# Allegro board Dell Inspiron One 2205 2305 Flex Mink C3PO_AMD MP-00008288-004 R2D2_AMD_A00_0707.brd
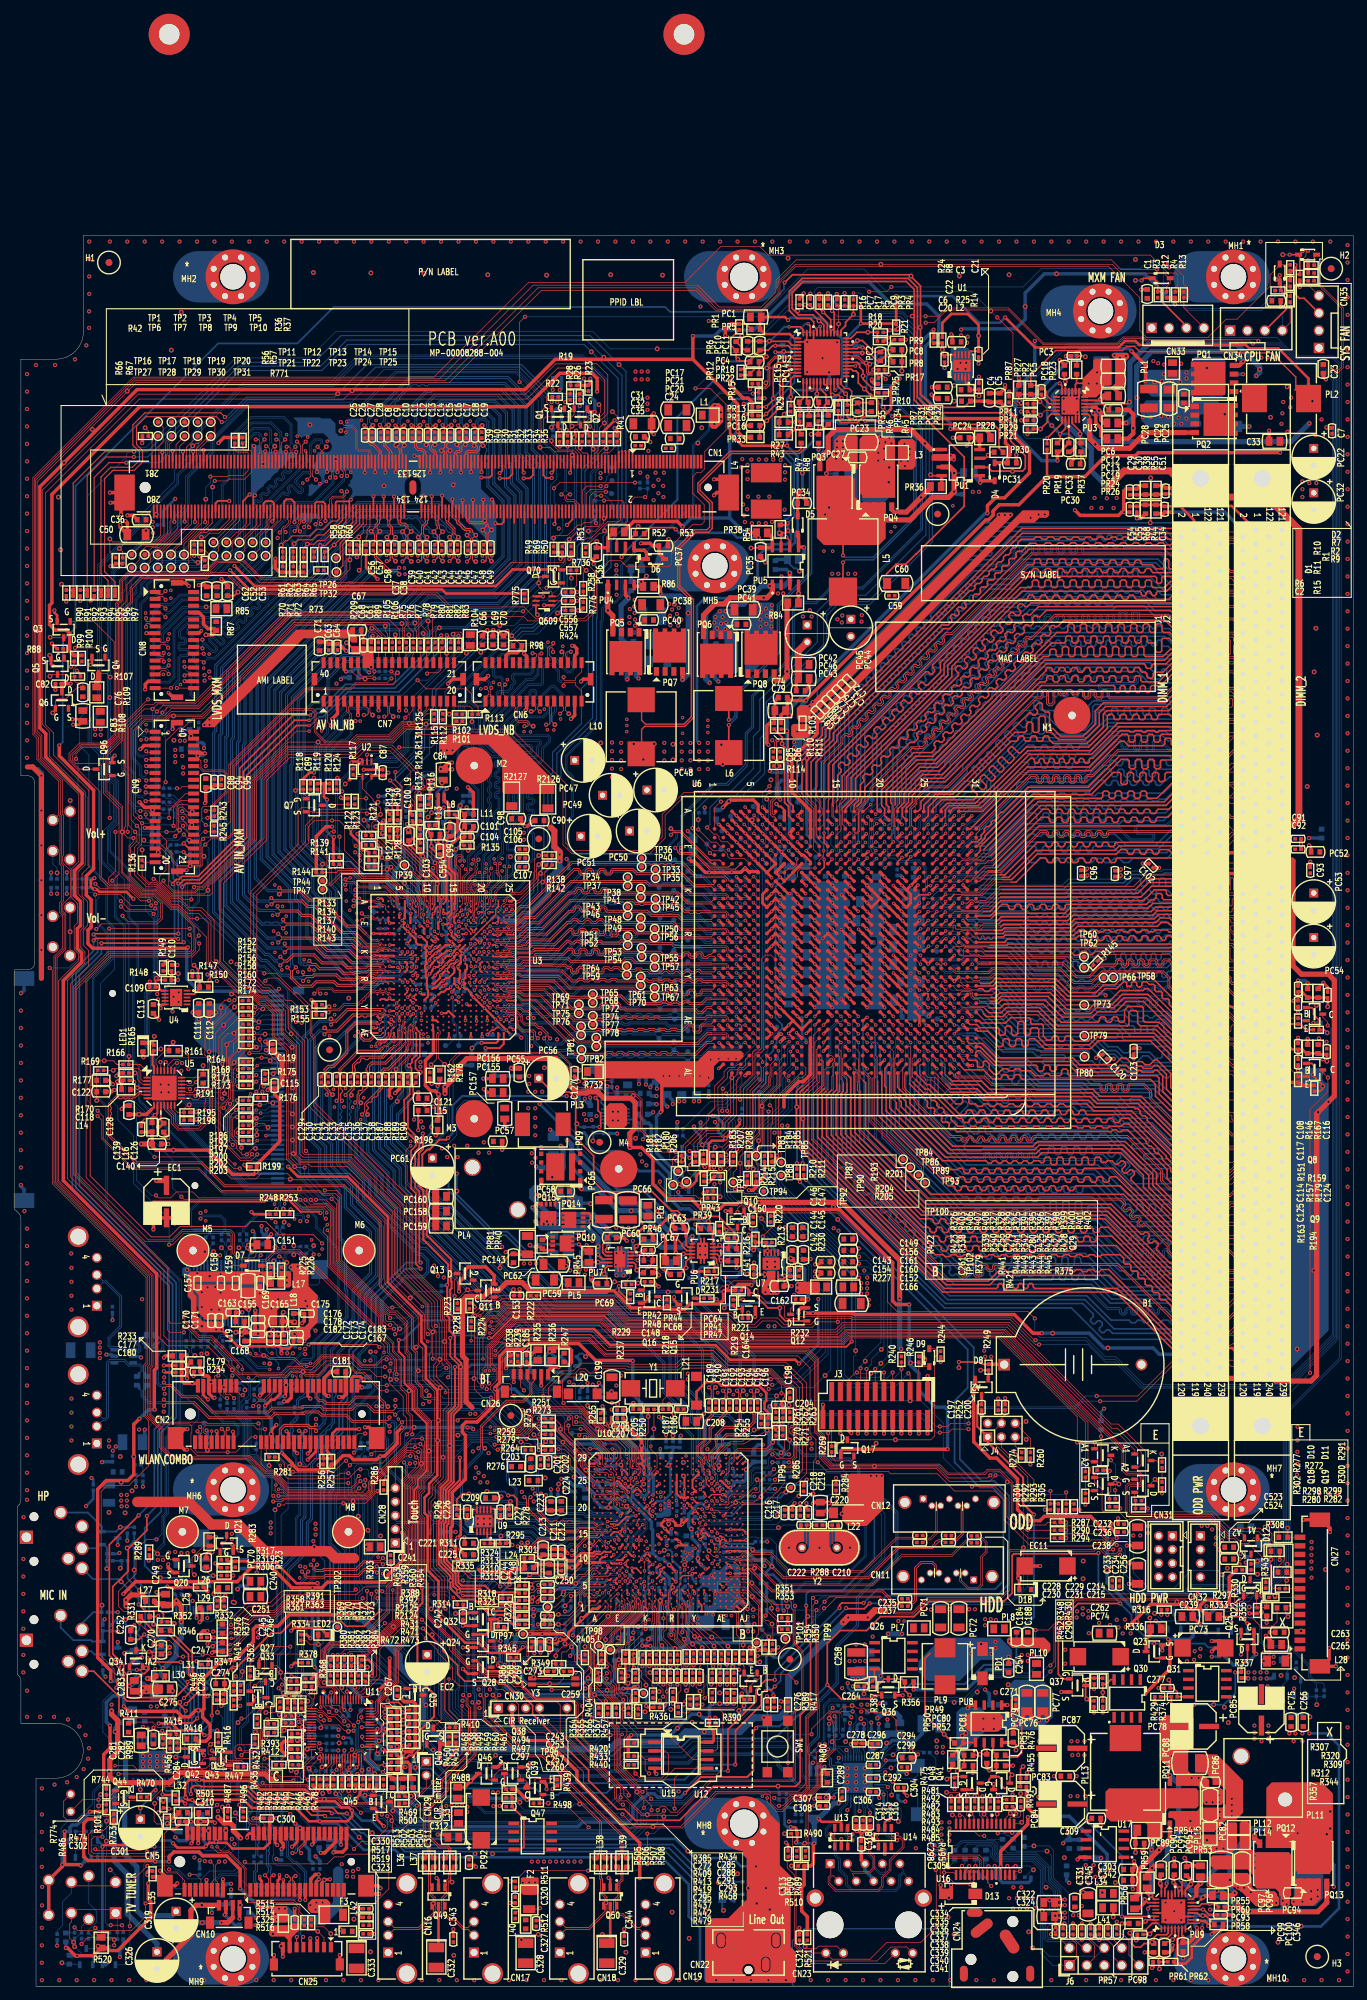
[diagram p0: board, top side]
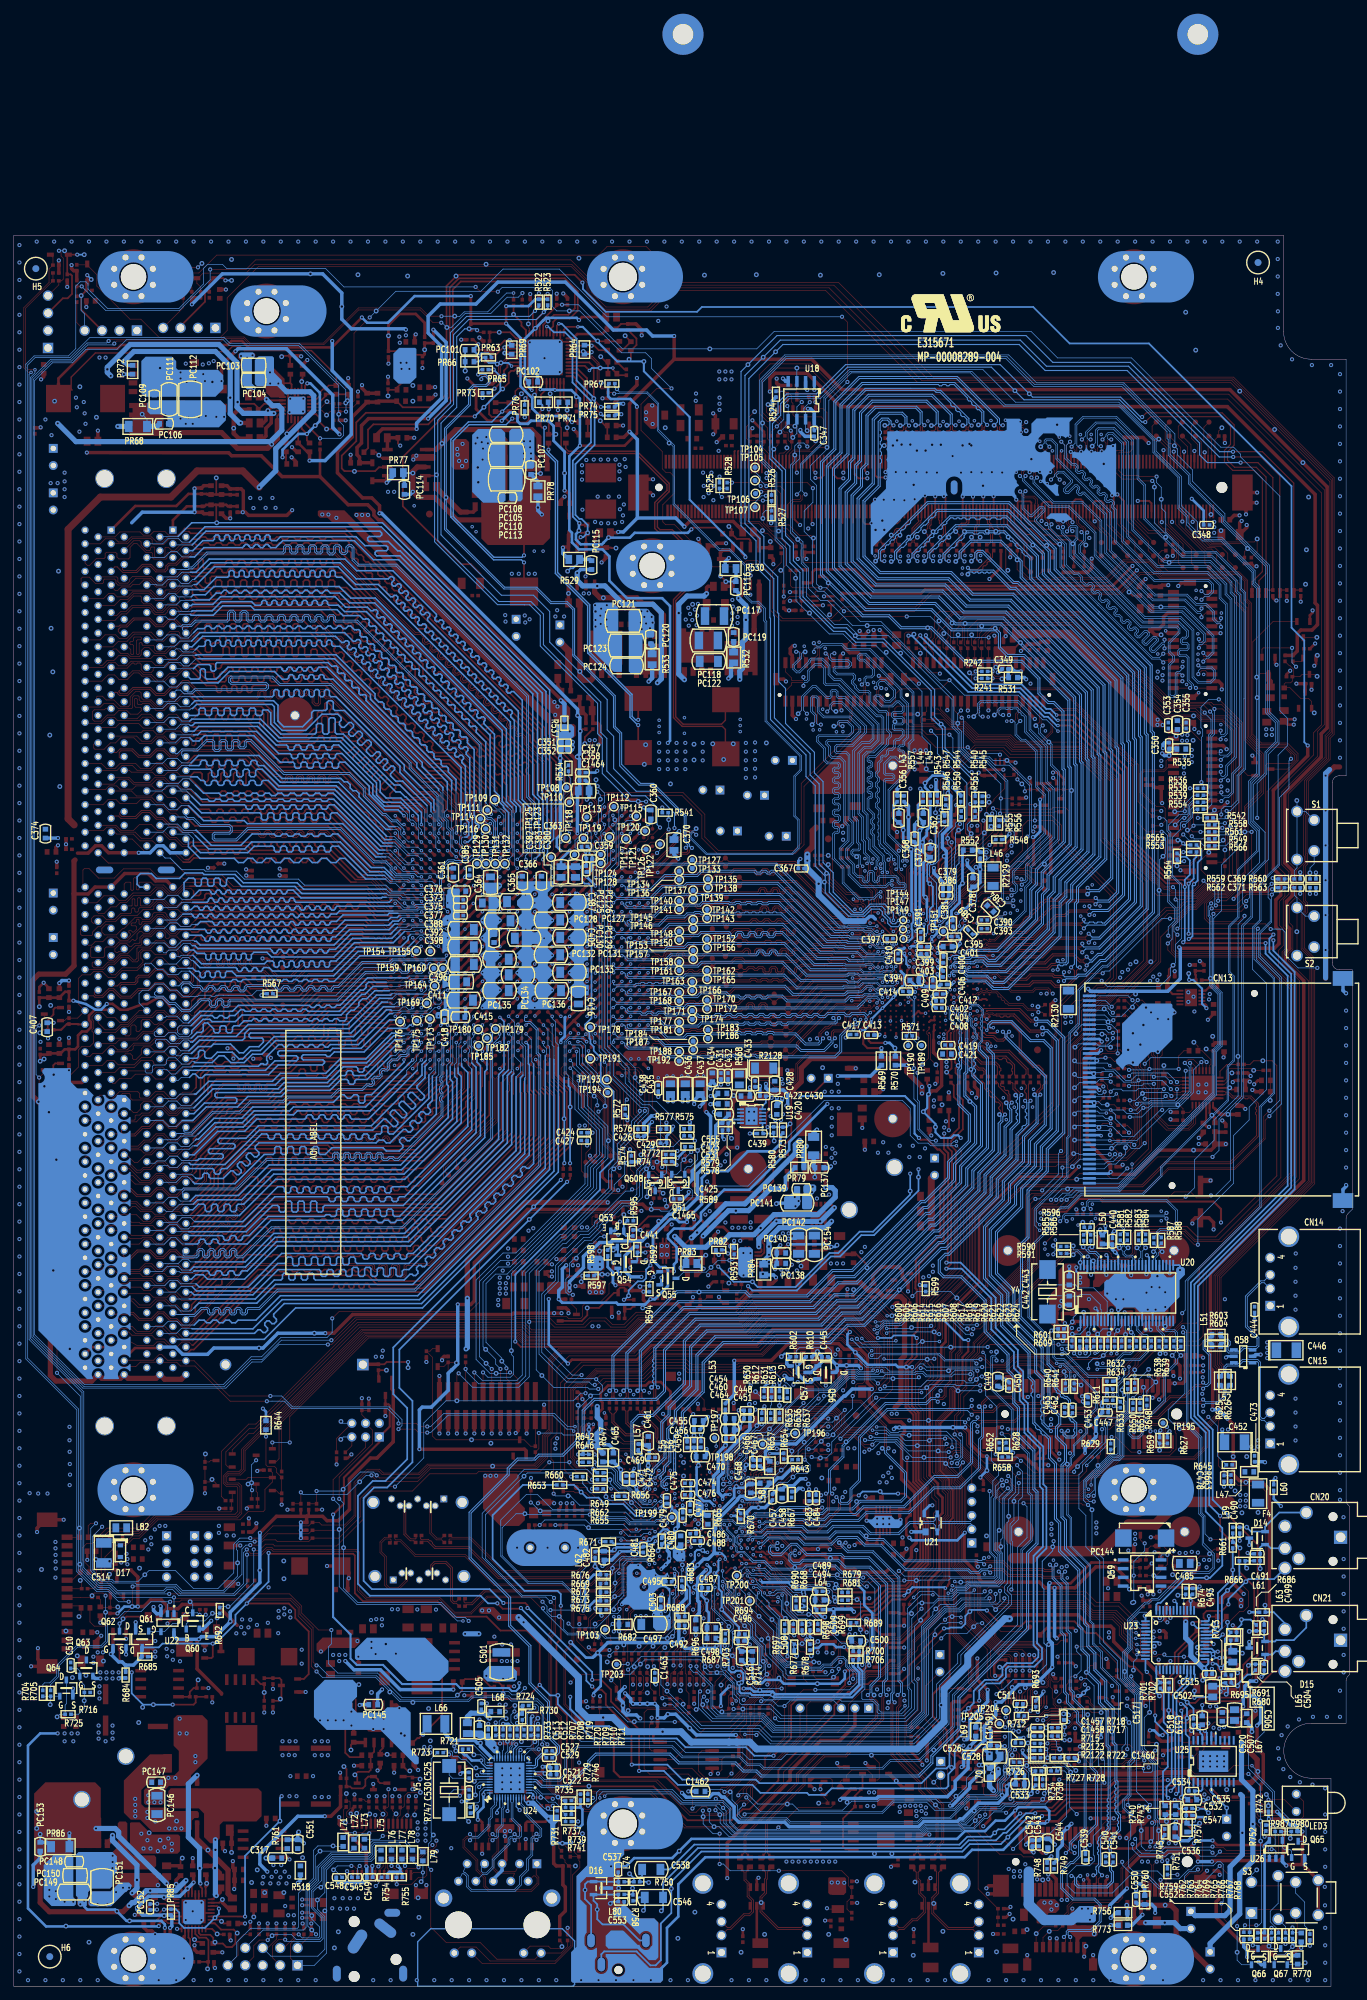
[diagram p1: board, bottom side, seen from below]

Outline 195 x 255 mm; copper layers: TOP, GND1, INT1, VCC, GND2, BOTTOM. Coordinates in mm from the lower left corner of the outline.
Outline path: 0,148.07 0,113.17 0.61,112.56 arc(0.82,112.24) 0.9,111.86 0.9,70.81 arc(0.82,70.43) 0.61,70.11 0.4,69.9 0.4,45.4 0.61,45.19 arc(0.82,44.87) 0.9,44.49 0.9,38.31 6,38.31 arc(10,34.31) 6,30.31 3.1,30.31 3.1,0 195,0 195,255 10,255 10,241 arc(8.83,238.17) 6,237 0.9,237 0.9,176.32 1.9,176.32 arc(2.61,176.03) 2.9,175.32 2.9,149.07 arc(2.61,148.36) 1.9,148.07 0,148.07

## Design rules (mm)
net group AMP_SVRR: nets AMP_SVRR N214468883
net group AU6433_RST_N: nets AU6433_RST_N N182697602
net group BLK_EN: nets BLK_EN N214902576
net group BLK_PWM: nets BLK_PWM N214902487
net group BT_DISABLE: nets BT_DISABLE BT_DISABLE_R
net group BT_DISABLE_N: nets BT_DISABLE_N N212412188
net group BT_LED: nets BT_LED N201793917
net group CARDREADER-MISC_12/12/12/A: nets SDCLK/XDALE/MSBS SDWP/XDCLE/MSCLK
net group CIR_BLTX_TIP_DRIVE: nets CIR_BLTX_TIP_DRIVE N195279140
net group COM1_C1N: nets COM1_C1N COM1_C1P
net group COM1_C2N: nets COM1_C2N COM1_C2P
net group COM1_RI_N: nets COM1_RI_N N216543933
net group CPU_FAN_PWM: nets CPU_FAN_PWM N201366217
net group CPU_PWRGD: nets N192993994 SYS_PWROK
net group CPU_TEST29_H_FBCLKOUT_H: nets CPU_TEST29_H_FBCLKOUT_H CPU_TEST29_L_FBCLKOUT_L
net group CTSA: nets CTSA CTSA_L
net group DCDA: nets DCDA DCDA_L
net group DDR3_P1V5_CS: nets DDR3_P1V5_CS DDR3_P1V5_FILT
net group DDSPC_HPD: nets DDSPC_HPD MXM_DDSPC_HPD
net group DSRA: nets DSRA DSRA_L
net group DTRA: nets DTRA DTRA_L
net group EAPD_MUTE_CTRL: nets EAPD_MUTE_CTRL N222289486
net group EEDO_LED3: nets EEDO_LED3 EEDO_LED3_R
net group EESK_LED1: nets EESK_LED1 EESK_LED1_R
net group FC_CLK_R: nets FC_CLK_R N182610771
net group FC_FBCLKOUT_R: nets FC_FBCLKOUT_R N182623261
net group GPON7: nets GPON7 N182698044
net group HDA_SPKR: nets N215117175 N224524412
net group HT_CTLIN1: nets HT_CTLIN1_N HT_CTLIN1_P
net group HT_CTLOUT1: nets HT_CTLOUT1_N HT_CTLOUT1_P
net group I2C_CLK: nets N184743934 NB_LCD_DDC_CLK
net group I2C_DATA: nets N184744092 NB_LCD_DDC_DATA
net group IHDA-ANALOG: nets JDREF_AUD N207033685
net group IHDA-ANALOG1_10/10/20/A: nets N199565995 N199565999
net group LAN_ACT_LED_N: nets LAN_ACT_LED_N LAN_ACT_LED_R_N
net group LAN_EVDD10: nets LAN_EVDD10 LAN_REGOUT
net group LED_AMBER_EN: nets LED_AMBER_EN N220115319
net group LVDDPWR_R_EN: nets LVDDPWR_R_EN N214797167
net group MIC_CLK: nets MIC_CLK MIC_CLK_R
net group MIC_DAT: nets MIC_DAT MIC_DAT_R
net group MISC-SPIFLASH: nets SPI_CLK SPI_CS_N
net group MXM_BLEN: nets MXM_BLEN N87830784
net group MXM_LVDS_DDC_CLK: nets MXM_LVDS_DDC_CLK N195453329
net group MXM_LVDS_DDC_DATA: nets MXM_LVDS_DDC_DATA N200059938
net group MXM_LVDS_PWM: nets MXM_LVDS_PWM N87830775
net group MXM_LVDSPWR_EN: nets MXM_LVDSPWR_EN N87830786
net group N192922017: nets N192922017 N192922462
net group N192922021: nets N192922021 N192922350
net group N192993947: nets N192993947 N192994078
net group N192994193: nets N192994193 N192994205
net group N192994229: nets N192994229 N192994300
net group N193056479: nets N193056479 N193056523
net group N193057135: nets N193057135 N193057441
net group N193064874: nets N193064874 N193064914
net group N193065496: nets N193065496 N197768843
net group N193065687: nets N193065687 N193065695
net group N193065785: nets N193065785 N193065828
net group N193066341: nets N193066341 N193066412
net group N193082220: nets N193082220 N193082234
net group N204332065: nets N204332065 N204332072
net group N208253507: nets N208253507 N208253520
net group NB_LCD_BKL_EN: nets NB_LCD_BKL_EN NB_LCD_BKL_EN_R
net group NB_LCD_BKL_PWM: nets NB_LCD_BKL_PWM NB_LCD_BKL_PWM_R
net group NB_LCD_PWR_EN: nets NB_LCD_PWR_EN NB_LCD_PWR_EN_R
net group P1V1_PWRGD: nets N204331910 P1V1_PWRGD
net group P1V5_DDR3_PWRGD: nets N205761624 P1V5_DDR3_PWRGD
net group P1V25_PWRGD: nets N192993988 P1V25_PWRGD
net group P2E_SLOT0_PRSNT_1_N: nets P2E_SLOT0_PRSNT_1_N P2E_SLOT0_PRSNT_1_N_R
net group P3V3_BAT: nets P3V3_BAT VBAT
net group P3V3_CARD: nets P3V3_CARD P3V3_CF33
net group P5V_USB5V1: nets USB_OC1 USB_OCP_2_4
net group P5V_USB5V3: nets USB_OC2 USB_OCP_5_9
net group P12V_STBY: nets N193082214 N193082230
net group P19V_CONVERTER: nets N215339663 N218776850
net group P19V_SYS_FILE: nets N193056457 P19V_SYS_FILE
net group PANEL_ID0: nets PANEL_ID0 PANEL_ID0_R
net group PANEL_ID1: nets PANEL_ID1 PANEL_ID1_R
net group PANEL_ID2: nets PANEL_ID2 PANEL_ID2_R
net group PCI_AD29: nets PCI_AD29 SB800_MEMHOT_N
net group PCIE-MISC_W4/A_PH: nets PCIE_CALRN_R PCIE_CALRP_R
net group PSON_N_1V5_CTRL: nets N193066078 PSON_N_1V5_CTRL
net group PSON_N_3V3_CTRL: nets N187384381 PSON_N_3V3_CTRL
net group PSON_N_5V_CTRL: nets N187384477 PSON_N_5V_CTRL
net group PSON_N_12V_CTRL: nets N211486769 PSON_N_12V_CTRL
net group PWRGD_PS: nets N188975577 PWRGD_PS
net group RIA: nets RIA RIA_L
net group RTSA: nets RTSA RTSA_L
net group RXDA: nets RXDA RXDA_L
net group SATA-CAL_W12.6-11/A_PH: nets SATA_CALRN SATA_CALRP
net group SB_PWRGD: nets N194724824 N222245969
net group SB_RTCRST_N: nets SB_RTCRST_N VBAT_IN
net group SD_D0/MMC_D0/MS_D0/XD_D0: nets N182697773 SD_D0/MMC_D0/MS_D0/XD_D0
net group SD_D3/MMC_D3/MS_D3/XD_D3: nets N182697771 SD_D3/MMC_D3/MS_D3/XD_D3
net group SD_D4/MMC_D4/MS_D4/XD_D4: nets N182697757 SD_D4/MMC_D4/MS_D4/XD_D4
net group SD_D5/MMC_D5/MS_D5/XD_D5: nets N182697749 SD_D5/MMC_D5/MS_D5/XD_D5
net group SD_D6/MMC_D6/MS_D6/XD_D6: nets N182697751 SD_D6/MMC_D6/MS_D6/XD_D6
net group SD_D7/MMC_D7/MS_D7/XD_D7: nets N182697755 SD_D7/MMC_D7/MS_D7/XD_D7
net group SDCDN/XDWRN: nets N182697812 SDCDN/XDWRN
net group SDCMD/XDRBN: nets N182697816 SDCMD/XDRBN
net group SIO_CIR_TX: nets N195279187 SIO_CIR_TX
net group SIO_KBCLK: nets N225179540 SIO_KBCLK
net group SIO_KBDATA: nets N225179544 SIO_KBDATA
net group SIO_MSECLK: nets N225179532 SIO_MSECLK
net group SIO_MSEDATA: nets N225179536 SIO_MSEDATA
net group SPDIF-OUT: nets SPDIF-OUT_MXM_R SPDIF-OUT_NB_R
net group SPEK_SUMOUT_L: nets SPEK_SUMOUT_L SUMOUT_L
net group SPI_DATAIN: nets SPI_DATAIN SPI_DI_R
net group SPM_CLKN: nets SPM_CLKN SPM_CLKP
net group SYS_FAN1_PWM: nets N208745698 SYS_FAN1_PWM
net group SYS_FAN_PWM: nets N201366255 SYS_FAN_PWM
net group TOUCH_PANEL_DETECT: nets N198554672 TOUCH_PANEL_DETECT
net group TXDA: nets TXDA TXDA_L
net group USB5V2: nets USB_OC0 USB_OCP_0_6
net group VDD0_NB_ENABLE: nets N192994176 VDD0_NB_ENABLE
net group VDDIO_P3V3_PCIGP: nets VDDIO_P3V3_PCIGP VDDPL_P3V3_SYS
net group VGA-DDC_W6.5/A_PH: nets MXM_VGA_DDC_CLK MXM_VGA_DDC_DATA
net group VRM_PWRGD: nets N194724769 VRM_PWRGD
net group XDWPN: nets N182697814 XDWPN
net group 2668_BK_ENA: nets 2668_BK_ENA 2668_BK_ENA_MXM_R 2668_BK_ENA_NB_R DDR3_P1V5_EN_S3 ENABKL ENABKL_R GPIO208_MXM_R GPIO208_NB_N N174239814 N214468931 N215339673 SLP_S3_N
net group 2668_BK_PWM: nets 2668_BK_PWM 2668_BK_PWM_MXM_R 2668_BK_PWM_NB_R BKL_PWM_R BRIGHT_ADJUST
net group 2668_DETECT_N: nets 2668_DETECT_N 2668_DETECT_N_MXM_R 2668_DETECT_N_NB_R
net group 2668_LVDD_EN: nets 2668_LVDD_EN 2668_LVDD_EN_MXM_R 2668_LVDD_EN_NB_R LVDDPWR_EN
net group AMP_IN_L: nets AMP_IN_L INL INL_MXM_R INL_NB_R
net group AMP_IN_R: nets AMP_IN_R INR_MXM_R INR_NB_R SPEK_SUMOUT_R SUMOUT_R
net group AMP_MODE: nets AMP_MODE N214468911 N214485400
net group AP_VOLUME_DOWN: nets AP_VOLUME_DOWN AP_VOLUME_DOWN_MXM_R AP_VOLUME_DOWN_NB_R
net group AP_VOLUME_UP: nets AP_VOLUME_UP AP_VOLUME_UP_MXM_R AP_VOLUME_UP_NB_R
net group AUDIO_INDICATE: nets AUDIO_INDICATE AUDIO_INDICATE_MXM_R AUDIO_INDICATE_NB_R
net group AUDIO_MUTE: nets AUDIO_MUTE AUDIO_MUTE_MXM_R AUDIO_MUTE_NB_R
net group AV_MODE: nets AV_MODE AV_MODE_MXM_R AV_MODE_NB_R
net group AZ_SDATA_OUT: nets P1V5_TV P1V5_WW SB_AZ_VDDIO SPM_COMPN VDDIO_AZ_S
net group CLK-14_W5.1-4.5/A_PH: nets CLK_REQG_N MXM_CLKREQ_N NB_OSC NB_OSC_R SB_OSC SB_OSC_R
net group CLK-33_W4-3.5/A_PH: nets CLK_PCI_33M_DEBUG CLK_PCI_33M_DEBUG_R CLK_PCI_33M_SIO PCI_CLK0 PCI_CLK1_R PCI_CLK2 PCI_CLK2_R PCI_CLK3 PCI_CLK3_R PCI_CLK4 PCI_CLK4_R
net group CLK-48_W5.1-4.5/A_PH: nets CLK_48M_CARD CLK_48M_SIO CLK_48M_USB N182698057 USB_48M_R
net group CLK-HOST_W5-4D6.2-5.5/A_PH: nets CLK_200M_CPU_DN CLK_200M_CPU_DN_R CLK_200M_CPU_DP CLK_200M_CPU_DP_R CPU_CLKIN_SC_N CPU_CLKIN_SC_P
net group CLK-SRC_W3.9-3.5D6.1-6/A_PH: nets CLK_100M_NBGFX_DN CLK_100M_NBGFX_DP CLK_100M_NBHT_DN CLK_100M_NBHT_DP CLK_100M_PCIE_LAN_DN CLK_100M_PCIE_LAN_DP CLK_100M_PCIE_TUNER_DN CLK_100M_PCIE_TUNER_DP CLK_100M_PCIE_WLAN_DN CLK_100M_PCIE_WLAN_DP GFX_CLK_DN GFX_CLK_DP NBLINK_RCLK_DN NBLINK_RCLK_DP SB_SRC_CLK_DN SB_SRC_CLK_DP
net group CLK-XTAL_W4-3.5/A_PH: nets 32K_X1 32K_X2 CLK_ICH_RTCX1 CLK_ICH_RTCX2 LAN_XTAL1 LAN_XTAL2 SATA_X1 SATA_X2
net group CLK_VDD: nets CLK_VDD PD# REF0/SEL_HTT6
net group CPU_CORE_TYPE: nets N192994066
net group CPU_HTREF1: nets N193064906
net group CPU_THERMDA: nets P3V3_AVCC_SIO REMOTE_P SIO_GND SIO_P5V_SENSE VREF_SIO
net group CPU_THERMTRIP_N: nets CPU_THERMTRIP_N CPU_THERMTRIP_R_N N221267533
net group CPU_VDDA_RUN_OUT: nets N193065820
net group DCIN: nets DCIN N192917727 VIN_19
net group DDR3_P1V5_DH: nets DDR3_P1V5_DH DDR3_P1V5_VBST N193073747 N193074055 N193074069
net group DDR3_P1V5_EN_S5: nets N212418796
net group DDR3A-ADDCMD_W9/B_PH: nets MEM_MA_ADD0 MEM_MA_ADD1 MEM_MA_ADD2 MEM_MA_ADD3 MEM_MA_ADD4 MEM_MA_ADD5 MEM_MA_ADD6 MEM_MA_ADD7 MEM_MA_ADD8 MEM_MA_ADD9 MEM_MA_ADD10 MEM_MA_ADD11 MEM_MA_ADD12 MEM_MA_ADD13 MEM_MA_ADD14 MEM_MA_ADD15 MEM_MA_BANK0 MEM_MA_BANK1 MEM_MA_BANK2 MEM_MA_CAS_N MEM_MA_RAS_N MEM_MA_WE_N
net group DDR3A-CLK_W5.1D5.6/B_PH: nets MEM_MA0_CLK0_N MEM_MA0_CLK0_P MEM_MA0_CLK1_N MEM_MA0_CLK1_P
net group DDR3A-CTRL_W9/B_PH: nets MEM_MA0_CS_L0 MEM_MA0_CS_L1 MEM_MA0_ODT0 MEM_MA0_ODT1 MEM_MA_CKE0 MEM_MA_CKE1
net group DDR3A-DQ_W9/B_PH: nets MEM_MA_CHECK0 MEM_MA_CHECK1 MEM_MA_CHECK2 MEM_MA_CHECK3 MEM_MA_CHECK4 MEM_MA_CHECK5 MEM_MA_CHECK6 MEM_MA_CHECK7 MEM_MA_DATA0 MEM_MA_DATA1 MEM_MA_DATA2 MEM_MA_DATA3 MEM_MA_DATA4 MEM_MA_DATA5 MEM_MA_DATA6 MEM_MA_DATA7 MEM_MA_DATA8 MEM_MA_DATA9 MEM_MA_DATA10 MEM_MA_DATA11 MEM_MA_DATA12 MEM_MA_DATA13 MEM_MA_DATA14 MEM_MA_DATA15 MEM_MA_DATA16 MEM_MA_DATA17 MEM_MA_DATA18 MEM_MA_DATA19 MEM_MA_DATA20 MEM_MA_DATA21 MEM_MA_DATA22 MEM_MA_DATA23 MEM_MA_DATA24 MEM_MA_DATA25 MEM_MA_DATA26 MEM_MA_DATA27 MEM_MA_DATA28 MEM_MA_DATA29 MEM_MA_DATA30 MEM_MA_DATA31 MEM_MA_DATA32 MEM_MA_DATA33 MEM_MA_DATA34 MEM_MA_DATA35 MEM_MA_DATA36 MEM_MA_DATA37 MEM_MA_DATA38 MEM_MA_DATA39 MEM_MA_DATA40 MEM_MA_DATA41 MEM_MA_DATA42 MEM_MA_DATA43 MEM_MA_DATA44 MEM_MA_DATA45 MEM_MA_DATA46 MEM_MA_DATA47 MEM_MA_DATA48 MEM_MA_DATA49 MEM_MA_DATA50 MEM_MA_DATA51 MEM_MA_DATA52 MEM_MA_DATA53 MEM_MA_DATA54 MEM_MA_DATA55 MEM_MA_DATA56 MEM_MA_DATA57 MEM_MA_DATA58 MEM_MA_DATA59 MEM_MA_DATA60 MEM_MA_DATA61 MEM_MA_DATA62 MEM_MA_DATA63 MEM_MA_DM0 MEM_MA_DM1 MEM_MA_DM2 MEM_MA_DM3 MEM_MA_DM4 MEM_MA_DM5 MEM_MA_DM6 MEM_MA_DM7 MEM_MA_DM8
net group DDR3A-DQS_W5.1D5.6/B_PH: nets MEM_MA_DQS0_N MEM_MA_DQS0_P MEM_MA_DQS1_N MEM_MA_DQS1_P MEM_MA_DQS2_N MEM_MA_DQS2_P MEM_MA_DQS3_N MEM_MA_DQS3_P MEM_MA_DQS4_N MEM_MA_DQS4_P MEM_MA_DQS5_N MEM_MA_DQS5_P MEM_MA_DQS6_N MEM_MA_DQS6_P MEM_MA_DQS7_N MEM_MA_DQS7_P MEM_MA_DQS8_N MEM_MA_DQS8_P
net group DDR3B-ADDCMD_W9/T_PH: nets MEM_MB_ADD0 MEM_MB_ADD1 MEM_MB_ADD2 MEM_MB_ADD3 MEM_MB_ADD4 MEM_MB_ADD5 MEM_MB_ADD6 MEM_MB_ADD7 MEM_MB_ADD8 MEM_MB_ADD9 MEM_MB_ADD10 MEM_MB_ADD11 MEM_MB_ADD12 MEM_MB_ADD13 MEM_MB_ADD14 MEM_MB_ADD15 MEM_MB_BANK0 MEM_MB_BANK1 MEM_MB_BANK2 MEM_MB_CAS_N MEM_MB_RAS_N MEM_MB_WE_N
net group DDR3B-CLK_W5.1D5.6/T_PH: nets MEM_MB0_CLK0_N MEM_MB0_CLK0_P MEM_MB0_CLK1_N MEM_MB0_CLK1_P
net group DDR3B-CTRL_W9/T_PH: nets MEM_MB0_CS_L0 MEM_MB0_CS_L1 MEM_MB0_ODT0 MEM_MB0_ODT1 MEM_MB_CKE0 MEM_MB_CKE1
net group DDR3B-DQ_W9/T_PH: nets MEM_MB_CHECK0 MEM_MB_CHECK1 MEM_MB_CHECK2 MEM_MB_CHECK3 MEM_MB_CHECK4 MEM_MB_CHECK5 MEM_MB_CHECK6 MEM_MB_CHECK7 MEM_MB_DATA0 MEM_MB_DATA1 MEM_MB_DATA2 MEM_MB_DATA3 MEM_MB_DATA4 MEM_MB_DATA5 MEM_MB_DATA6 MEM_MB_DATA7 MEM_MB_DATA8 MEM_MB_DATA9 MEM_MB_DATA10 MEM_MB_DATA11 MEM_MB_DATA12 MEM_MB_DATA13 MEM_MB_DATA14 MEM_MB_DATA15 MEM_MB_DATA16 MEM_MB_DATA17 MEM_MB_DATA18 MEM_MB_DATA19 MEM_MB_DATA20 MEM_MB_DATA21 MEM_MB_DATA22 MEM_MB_DATA23 MEM_MB_DATA24 MEM_MB_DATA25 MEM_MB_DATA26 MEM_MB_DATA27 MEM_MB_DATA28 MEM_MB_DATA29 MEM_MB_DATA30 MEM_MB_DATA31 MEM_MB_DATA32 MEM_MB_DATA33 MEM_MB_DATA34 MEM_MB_DATA35 MEM_MB_DATA36 MEM_MB_DATA37 MEM_MB_DATA38 MEM_MB_DATA39 MEM_MB_DATA40 MEM_MB_DATA41 MEM_MB_DATA42 MEM_MB_DATA43 MEM_MB_DATA44 MEM_MB_DATA45 MEM_MB_DATA46 MEM_MB_DATA47 MEM_MB_DATA48 MEM_MB_DATA49 MEM_MB_DATA50 MEM_MB_DATA51 MEM_MB_DATA52 MEM_MB_DATA53 MEM_MB_DATA54 MEM_MB_DATA55 MEM_MB_DATA56 MEM_MB_DATA57 MEM_MB_DATA58 MEM_MB_DATA59 MEM_MB_DATA60 MEM_MB_DATA61 MEM_MB_DATA62 MEM_MB_DATA63 MEM_MB_DM0 MEM_MB_DM1 MEM_MB_DM2 MEM_MB_DM3 MEM_MB_DM4 MEM_MB_DM5 MEM_MB_DM6 MEM_MB_DM7 MEM_MB_DM8
net group DDR3B-DQS_W5.1D5.6/T_PH: nets MEM_MB_DQS0_N MEM_MB_DQS0_P MEM_MB_DQS1_N MEM_MB_DQS1_P MEM_MB_DQS2_N MEM_MB_DQS2_P MEM_MB_DQS3_N MEM_MB_DQS3_P MEM_MB_DQS4_N MEM_MB_DQS4_P MEM_MB_DQS5_N MEM_MB_DQS5_P MEM_MB_DQS6_N MEM_MB_DQS6_P MEM_MB_DQS7_N MEM_MB_DQS7_P MEM_MB_DQS8_N MEM_MB_DQS8_P
net group DRV_P0_ENABLE: nets DRV_P0_ENABLE N192922344 N192922456
net group EAR_L_FIL: nets HP_L
net group EAR_R_FIL: nets HP_R
net group EXT_PCIE_LAN_CLKREQ_N: nets EXT_PCIE_LAN_CLKREQ_N PCIE_LAN_CLKREQ_N SB_PCIE_LAN_CLKREQ_N
net group HDMI_W3.9D6.1/A_PH: nets MXM_DDSP_CLK_DN MXM_DDSP_CLK_DP MXM_DDSP_TX0_DN MXM_DDSP_TX0_DP MXM_DDSP_TX1_DN MXM_DDSP_TX1_DP MXM_DDSP_TX2_DN MXM_DDSP_TX2_DP NB_HDMI_CLK_TX3_DN NB_HDMI_CLK_TX3_DP PCIE_NB_HDMI_TX0_DN PCIE_NB_HDMI_TX0_DP PCIE_NB_HDMI_TX1_DN PCIE_NB_HDMI_TX1_DP PCIE_NB_HDMI_TX2_DN PCIE_NB_HDMI_TX2_DP
net group HP_SENSE: nets SENSE_B
net group HT-MISC: nets AVDDDI AVDDQ CPU_TEST25_H_BYPASSCLK_H DDC_CLK0 MEM_MA_EVENT_L MEM_MB_EVENT_L N56144747 N193065727 PLLVDD18 VDD18 VDDA18HTPLL VDDA18PCIEPLL VDDHTTX VDDIO_P1V8_FC VDDLT18 VDDLTP18
net group HT-MISC3_12/12/12/A: nets A_RST_N CPU_PRESENT_N CPU_PRESENT_R_N CPU_PWRGD LDT_RST_D_N LDT_RST_N N198880140 NB_RST_IN_N SB_A_RST_N
net group HT-MISC_W4/A_PH: nets ALLOW_LDTSTOP CPU_ALERT_N CPU_CORE_TYPE CPU_DBRDY CPU_DBREQ_N CPU_HTREF0 CPU_HTREF1 CPU_M_ZN CPU_M_ZP CPU_PROCHOT_1.5_N CPU_PROCHOT_1.5_R_N CPU_PSI_N CPU_SIC CPU_SID CPU_SVC CPU_SVD CPU_TCK CPU_TDI CPU_TDO CPU_THERMTRIP_L CPU_TMS CPU_TRST_N CPU_VDDR_SUS_SENSE HT_RXCALN HT_RXCALP HT_TXCALN HT_TXCALP I2C_CLK I2C_DATA LDT_STOP_N M_VDDIO_PWRGD NB_ALLOW_LDTSTOP NB_LDT_STOP_N SA0 VDDG_NB
net group HT-THERM_W10/A_PH: nets CPU_THERMDA CPU_THERMDA_R CPU_THERMDC CPU_THERMDC_R N183186081
net group HT-VDDNB_W4D4/A_PH: nets CPU_VDD_FB_H CPU_VDD_FB_L CPU_VDDNB_RUN_FB_H CPU_VDDNB_RUN_FB_L N192994062 N192995298
net group HT_W5D6.2/A_PH: nets HT_CADIN0_N HT_CADIN0_P HT_CADIN1_N HT_CADIN1_P HT_CADIN2_N HT_CADIN2_P HT_CADIN3_N HT_CADIN3_P HT_CADIN4_N HT_CADIN4_P HT_CADIN5_N HT_CADIN5_P HT_CADIN6_N HT_CADIN6_P HT_CADIN7_N HT_CADIN7_P HT_CADIN8_N HT_CADIN8_P HT_CADIN9_N HT_CADIN9_P HT_CADIN10_N HT_CADIN10_P HT_CADIN11_N HT_CADIN11_P HT_CADIN12_N HT_CADIN12_P HT_CADIN13_N HT_CADIN13_P HT_CADIN14_N HT_CADIN14_P HT_CADIN15_N HT_CADIN15_P HT_CADOUT0_N HT_CADOUT0_P HT_CADOUT1_N HT_CADOUT1_P HT_CADOUT2_N HT_CADOUT2_P HT_CADOUT3_N HT_CADOUT3_P HT_CADOUT4_N HT_CADOUT4_P HT_CADOUT5_N HT_CADOUT5_P HT_CADOUT6_N HT_CADOUT6_P HT_CADOUT7_N HT_CADOUT7_P HT_CADOUT8_N HT_CADOUT8_P HT_CADOUT9_N HT_CADOUT9_P HT_CADOUT10_N HT_CADOUT10_P HT_CADOUT11_N HT_CADOUT11_P HT_CADOUT12_N HT_CADOUT12_P HT_CADOUT13_N HT_CADOUT13_P HT_CADOUT14_N HT_CADOUT14_P HT_CADOUT15_N HT_CADOUT15_P HT_CLKIN0_N HT_CLKIN0_P HT_CLKIN1_N HT_CLKIN1_P HT_CLKOUT0_N HT_CLKOUT0_P HT_CLKOUT1_N HT_CLKOUT1_P HT_CTLIN0_N HT_CTLIN0_P HT_CTLOUT0_N HT_CTLOUT0_P
net group IHDA-ANALOG2_W10/A_PH: nets EAR_L_FIL EAR_R_FIL HDA_SPKR HP_SENSE INR LINE_SENSE MIC1_JD MIC1_L MIC1_L_FIL MIC1_R MIC1_R_FIL N185663595 N185663597 N196851843 N208938368 N208939242 PC_BEEP PC_BEEP_SPEAKER SENSE_A SPDIF-OUT VREF_AUD
net group IHDA_W4.01-5.01/A_PH: nets AZ_BIT_CLK AZ_BIT_CLK_R AZ_RST_N AZ_RST_R_N AZ_SDATA_IN0 AZ_SDATA_IN1 AZ_SDATA_IN1_R AZ_SDATA_IN2 AZ_SDATA_OUT AZ_SDOUT_R AZ_SYNC AZ_SYNC_R
net group IOPLLVDD(NC): nets IOPLLVDD(NC) N52255643 N205761409 N205761490 N205761590 N205761636 N205761638 N205761660 N205761662 N205761686 PCE_CALRN PLLVDD REFCLK_N
net group LAN_W3.9D6.1/A_PH: nets LAN_MDI0_DN LAN_MDI0_DP LAN_MDI1_DN LAN_MDI1_DP LAN_MDI2_DN LAN_MDI2_DP LAN_MDI3_DN LAN_MDI3_DP
net group LCDVCC: nets LCDVCC_DISCHARGHE M704_1 N195361688 N195454034
net group LINE_L: nets LINE_L LINE_L_FIL N200259909 N200335513
net group LINE_R: nets LINE_R LINE_R_FIL N200335304 N208289349
net group LPC_W4/A_PH: nets LAD0 LAD0_R LAD1 LAD1_R LAD2 LAD2_R LAD3 LAD3_R LPC_LFRAME_N LPC_LFRAME_R_N N183418576 SERIRQ SIO_LPC_LAD0 SIO_LPC_LAD1 SIO_LPC_LAD2 SIO_LPC_LAD3
net group LVDS_W3.9D6.1/A_PH: nets MXM_LVDS_L_CLK_DN MXM_LVDS_L_CLK_DP MXM_LVDS_L_TX0_DN MXM_LVDS_L_TX0_DP MXM_LVDS_L_TX1_DN MXM_LVDS_L_TX1_DP MXM_LVDS_L_TX2_DN MXM_LVDS_L_TX2_DP MXM_LVDS_L_TX3_DN MXM_LVDS_L_TX3_DP MXM_LVDS_U_CLK_DN MXM_LVDS_U_CLK_DP MXM_LVDS_U_TX0_DN MXM_LVDS_U_TX0_DP MXM_LVDS_U_TX1_DN MXM_LVDS_U_TX1_DP MXM_LVDS_U_TX2_DN MXM_LVDS_U_TX2_DP MXM_LVDS_U_TX3_DN MXM_LVDS_U_TX3_DP NB_LVDS_L_CLK_DN NB_LVDS_L_CLK_DP NB_LVDS_L_TX0_DN NB_LVDS_L_TX0_DP NB_LVDS_L_TX1_DN NB_LVDS_L_TX1_DP NB_LVDS_L_TX2_DN NB_LVDS_L_TX2_DP NB_LVDS_L_TX3_DN NB_LVDS_L_TX3_DP NB_LVDS_U_CLK_DN NB_LVDS_U_CLK_DP NB_LVDS_U_TX0_DN NB_LVDS_U_TX0_DP NB_LVDS_U_TX1_DN NB_LVDS_U_TX1_DP NB_LVDS_U_TX2_DN NB_LVDS_U_TX2_DP NB_LVDS_U_TX3_DN NB_LVDS_U_TX3_DP
net group MIC1_L: nets N208403148
net group MIC1_R: nets N208402932
net group MISC-HWM: nets NB_VDDHT VDD_PCIE VDDHTRX
net group MISC-HWM_8/8/8/A: nets P2V5_CPU_VDDA_RUN
net group MISC-HWM_W4/A_PH: nets CLPCLK0_R CLPCLK1_R DBGSELECT2 GPIO199 GPIO200 LPC_CLK0 LPC_CLK1 SB_TEST0 SB_TEST1 SB_TEST2 VIN0 VIN1 VIN2 VIN3 VIN4 VIN5 VIN6
net group MISC-NB_W10/A_PH: nets N183186300 NB_THERMDA NB_THERMDA_R NB_THERMDC NB_THERMDC_R
net group MISC-SPIFLASH_W4/A_PH: nets SPI_DATAOUT
net group MISC_W4/A_PH: nets DDR3_P1V5_EN_S5 EC_A20M_N FP_RST_N FP_RST_R_N INTR_ALERT_N KB_RST_N N174239812 N188827131 N196390709 NB_PWRGD NB_PWRGD_IN P5V_USB_CTL PCIE_RST_N PCIE_RST_R_N PSOUT_SIO_N RSMRST_N SB_PWRGD SCLK1 SCLK2 SDA2 SDATA1 SIO_PSOUT_N SIO_RSMRST_N SIO_SMB_CLK SIO_SMB_DATA SLP_S5_N SMB_CLK_SUS SMB_DATA_SUS SP_DDR3_RST_N SUS_STAT_N SUS_STAT_R_N
net group MXM_PWRGD: nets MXM_PWR_GOOD MXM_PWRGD MXM_PWRGD_R
net group MXM_RST_N: nets MXM_RST_N N228265287 PCIE_RST_TV_N PCIE_RST_WLAN_N PERSTB RST_PLTRST_N SIO_RSTOUT0_N
net group N192993980: nets N192993980 N192994032 N192994094 N192994292 N192995254 N192995372
net group N192994026: nets N192994026 N192994068 N192994131 N192994369 N192994816 N192995282
net group N193056421: nets N193056421 N193056423 N193056459
net group N193057155: nets N193057155 N193057159 N193057437 N193057451
net group N193073716: nets N193073716
net group N193081910: nets N193082279
net group N204331890: nets N204331892 N204331919 N204331920 N204331931 N204331932
net group NB_PWRGD: nets N194724856
net group NB_PWRGD_IN: nets N194724902
net group P0V75_VTT_SUS: nets N193073929
net group P1V1ALW: nets N193066404 VDDAN_1.1V_USB_S VDDCR_P1V1_GBE_S VDDCR_P1V1_S VDDCR_P1V1_USB_S VDDPL_P1V1_SYS_S
net group P3V3_AUDIO_DVDD: nets N185605081
net group P3V3_STB_EN: nets P3V3_STB_EN P5V_LDO P5V_STB_EN
net group P5V_AUDIO_AVDD: nets N193522844 N220126171 PWR_ACT_LED1_WHITE PWR_ACT_LED1_WHITE_R PWR_ACT_LED_AMBER PWR_ACT_LED_AMBER_R
net group P12V: nets N192922358 N192922466 N192993943 N192994181 N222245952
net group PC_MODE: nets PC_MODE PC_MODE_MXM_R PC_MODE_NB_R
net group PC_STATUS: nets PC_STATUS PC_STATUS_MXM_R PC_STATUS_NB_R
net group PCI_RST_N: nets N183418266 PCI_RST_N PCI_RST_R_N SB_PCI_RST_R_N
net group PCIE_W6-5D5.5/A_PH: nets A_RX0N A_RX0N_C A_RX0P A_RX0P_C A_RX1N A_RX1N_C A_RX1P A_RX1P_C A_RX2N A_RX2N_C A_RX2P A_RX2P_C A_RX3N A_RX3N_C A_RX3P A_RX3P_C A_TX0N A_TX0N_C A_TX0P A_TX0P_C A_TX1N A_TX1N_C A_TX1P A_TX1P_C A_TX2N A_TX2N_C A_TX2P A_TX2P_C A_TX3N A_TX3N_C A_TX3P A_TX3P_C GFX_TX8N_C GFX_TX8P_C GFX_TX9N_C GFX_TX9P_C GFX_TX10N_C GFX_TX10P_C GFX_TX11N_C GFX_TX11P_C GFX_TX12N_C GFX_TX12P_C GFX_TX13N_C GFX_TX13P_C GFX_TX14N_C GFX_TX14P_C GFX_TX15N_C GFX_TX15P_C GPP_TX0N_C GPP_TX0P_C GPP_TX1N_C GPP_TX1P_C GPP_TX2N_C GPP_TX2P_C PCIE_MXM_NB_RX8N PCIE_MXM_NB_RX8N_C PCIE_MXM_NB_RX8P PCIE_MXM_NB_RX8P_C PCIE_MXM_NB_RX9N PCIE_MXM_NB_RX9N_C PCIE_MXM_NB_RX9P PCIE_MXM_NB_RX9P_C PCIE_MXM_NB_RX10N PCIE_MXM_NB_RX10N_C PCIE_MXM_NB_RX10P PCIE_MXM_NB_RX10P_C PCIE_MXM_NB_RX11N PCIE_MXM_NB_RX11N_C PCIE_MXM_NB_RX11P PCIE_MXM_NB_RX11P_C PCIE_MXM_NB_RX12N PCIE_MXM_NB_RX12N_C PCIE_MXM_NB_RX12P PCIE_MXM_NB_RX12P_C PCIE_MXM_NB_RX13N PCIE_MXM_NB_RX13N_C PCIE_MXM_NB_RX13P PCIE_MXM_NB_RX13P_C PCIE_MXM_NB_RX14N PCIE_MXM_NB_RX14N_C PCIE_MXM_NB_RX14P PCIE_MXM_NB_RX14P_C PCIE_MXM_NB_RX15N PCIE_MXM_NB_RX15N_C PCIE_MXM_NB_RX15P PCIE_MXM_NB_RX15P_C PCIE_NB_MXM_TX8N PCIE_NB_MXM_TX8P PCIE_NB_MXM_TX9N PCIE_NB_MXM_TX9P PCIE_NB_MXM_TX10N PCIE_NB_MXM_TX10P PCIE_NB_MXM_TX11N PCIE_NB_MXM_TX11P PCIE_NB_MXM_TX12N PCIE_NB_MXM_TX12P PCIE_NB_MXM_TX13N PCIE_NB_MXM_TX13P PCIE_NB_MXM_TX14N PCIE_NB_MXM_TX14P PCIE_NB_MXM_TX15N PCIE_NB_MXM_TX15P PCIE_NIC_RX_DN0 PCIE_NIC_RX_DP0 PCIE_NIC_TX_DN0 PCIE_NIC_TX_DP0 PCIE_TUNER_RX_DN1 PCIE_TUNER_RX_DP1 PCIE_TUNER_TX_DN1 PCIE_TUNER_TX_DP1 PCIE_WLAN_RX_DN2 PCIE_WLAN_RX_DP2 PCIE_WLAN_TX_DN2 PCIE_WLAN_TX_DP2 PE6_LAN_RXN_C PE6_LAN_RXP_C
net group PCIE_WAKE_MXM_N: nets PCIE_WAKE_MXM_N PCIE_WAKE_N PCIE_WAKE_TV_N PCIE_WAKE_WLAN_N PE_WAKE_NIC_N
net group PSOUT_SIO_N: nets PWRBTN_R_N PWRBTN_SIO_N SIO_PSIN_N
net group PWM1_P0_SENSE_N: nets N192922340 N192922354 N192922424 N192994036 PWM1_P0_SENSE_N PWM1_P0_SENSE_P
net group PWM3_P0_SENSE_N: nets N192922382 N192922384 N192922446 N194450047 PWM3_P0_SENSE_N PWM3_P0_SENSE_P
net group PWR_ACT_LED1_N: nets N215440771 N219210322 N219249647 N220111595 N222009354 N222009357 PWR_ACT_LED1_N PWR_ACT_LED_N SIO_GRN_LED SIO_YLW_LED
net group SATA-RX_W5.1-4.1D5.6-5/A_PH: nets SATA_RXN0 SATA_RXN1 SATA_RXP0 SATA_RXP1
net group SATA-TX_W3.9-3.5D6.1-6/A_PH: nets SATA_TXN0 SATA_TXN1 SATA_TXP0 SATA_TXP1
net group SD_D1/MMC_D1/MS_D1/XD_D1: nets N182697767 N182697808 SD_D1/MMC_D1/MS_D1/XD_D1
net group SD_D2/MMC_D2/MS_D2/XD_D2: nets N182697769 N182697810 SD_D2/MMC_D2/MS_D2/XD_D2
net group SDCLK/XDALE/MSBS: nets N182697659 SDCLK/XDALE/MSBS_P35_R SDCLK/XDALE/MSBS_R
net group SDWP/XDCLE/MSCLK: nets N182697747 N182697803 N182697915
net group SMB_CLK_MAIN: nets SMB_CLK_MAIN SMB_CLK_MAIN_R SMB_CLK_WLAN_R
net group SMB_DATA_MAIN: nets SMB_DATA_MAIN SMB_DATA_MAIN_R SMB_DATA_WLAN_R
net group SPK_L-P: nets SPK_L-P
net group SPK_R-N: nets SPK_R-N
net group USB-BIAS_W12.6-11/A_PH: nets USB_RCOMP_R
net group USB_W5.1-4.1D5.6-5/A_PH: nets USB_0N USB_0P USB_1N USB_1P USB_2N USB_2P USB_3N USB_3P USB_4N USB_4P USB_5N USB_5P USB_6N USB_6P USB_7N USB_7P USB_8N USB_8P USB_9N USB_9P USB_10N USB_10P USB_11N USB_11P USB_SB_REAR_P_DN2_FILTER USB_SB_REAR_P_DN4_FILTER USB_SB_REAR_P_DN5_FILTER USB_SB_REAR_P_DN9_FILTER USB_SB_REAR_P_DP2_FILTER USB_SB_REAR_P_DP4_FILTER USB_SB_REAR_P_DP5_FILTER USB_SB_REAR_P_DP9_FILTER
net group VDD0_NB_CS: nets N192994197 N192994201 N192994203 N192994235 VDD0_NB_CS
net group VDDIO_P3V3_S: nets VDDXL_P3V3_S
net group VGA-DDC_W10/A_PH: nets DAC_RSET
net group VGA-RGB_W6.5/A_PH: nets NB_VGA_B NB_VGA_G NB_VGA_R VGA_BLUE VGA_GREEN VGA_RED
net group VGA-SYNC_W6.5/A_PH: nets HSYNC HSYNC_N VSYNC VSYNC_N
net group XDRDN/MSINS: nets N182697759 N182697798 XDRDN/MSINS
nets with their own width: min track width 0.381; nets MEMA_VREFCA_SUS MEMA_VREFDQ_SUS MEMB_VREFCA_SUS MEMB_VREFDQ_SUS
nets with their own width: min track width 0.508; nets VDDIO_GBE_S VDDIO_P3V3_S
nets with their own width: min track width 0.635; nets VDDA18PCIE
nets with their own width: min track width 0.762; nets AVDD33_LAN LAN_VDD10 LCDVCC LCDVCC_1 P3V3_AUDIO_DVDD P5V_AUDIO_AVDD V_AMP VCT_LAN VDDAN_P1V1_CLK
nets with their own width: min track width 1.016; nets P5V_USB5V1 P5V_USB5V3 USB5V2
nets with their own width: min track width 1.27; nets VDDAN_P1V1_PCIE VDDAN_P3V3_USB_S
nets with their own width: min track width 2.032; nets VDDAN_P1V1_SATA
nets with their own width: min track width 2.54; nets VDDCR_P1V1

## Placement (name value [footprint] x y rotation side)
B1  BATT2P  [SKT_BAT2032]  156.22 90.55 180 top
C1  10UF  [C0603]  164.98 246.51 90 top
C2  10UF  [C0603]  183.78 245.49 0 top
C3  10UF  [C0603]  137.23 239.52 180 top
C4  10UF  [C0603]  142 231.39 90 top
C5  10UF  [C0603]  143.52 231.39 90 top
C6  10UF  [C0603]  135.2 232.92 180 top
C7  1UF  [C0402]  191.91 226.57 90 top
C8  0.1UF  [C0402]  55.6 225.93 90 top
C9  0.1UF  [C0402]  56.62 225.93 90 top
C10  0.1UF  [C0402]  57.89 225.93 90 top
C11  0.1UF  [C0402]  58.91 225.93 90 top
C12  0.1UF  [C0402]  60.18 225.93 90 top
C13  0.1UF  [C0402]  61.19 225.93 90 top
C14  0.1UF  [C0402]  62.46 225.93 90 top
C15  0.1UF  [C0402]  63.48 225.93 90 top
C16  0.1UF  [C0402]  64.75 225.93 90 top
C17  0.1UF  [C0402]  65.76 225.93 90 top
C18  0.1UF  [C0402]  67.03 225.93 90 top
C19  0.1UF  [C0402]  68.05 225.93 90 top
C20  10UF  [C0603]  135.2 231.27 180 top
C21  0.1UF  [C0402]  140.41 237.74 270 top
C22  1UF  [C0402]  135.46 236.98 270 top
C23  10UF  [C0603]  190.64 235.59 270 top
C24  3.3PF  [C0402]  95.26 224.03 0 top
C25  0.1UF  [C0402]  51.03 225.93 90 top
C26  0.1UF  [C0402]  52.05 225.93 90 top
C27  0.1UF  [C0402]  53.32 225.93 90 top
C28  0.1UF  [C0402]  54.33 225.93 90 top
C29  0.1UF  [C0402]  162.44 217.68 90 top
C30  1000PF  [C0402]  163.46 217.68 90 top
C31  10UF  [C1206]  91.45 227.58 0 top
C32  0.1UF  [C0603]  91.07 225.68 0 top
C33  10UF  [C0805]  183.53 225.04 180 top
C34  0.1UF  [C0402]  167.52 215.14 90 top
C35  3.3PF  [C0402]  90.82 224.41 180 top
C36  0.1UF  [C0603]  18.49 213.61 180 top
C37  0.1UF  [C0402]  55.35 209.55 90 top
C38  0.1UF  [C0402]  56.62 209.55 90 top
C39  0.1UF  [C0402]  57.64 209.55 90 top
C40  0.1UF  [C0402]  58.91 209.55 90 top
C41  0.1UF  [C0402]  59.92 209.55 90 top
C42  0.1UF  [C0402]  61.19 209.55 90 top
C43  0.1UF  [C0402]  62.21 209.55 90 top
C44  0.1UF  [C0402]  63.48 209.55 90 top
C45  0.1UF  [C0402]  64.49 209.55 90 top
C46  0.1UF  [C0402]  66.02 209.55 90 top
C47  0.1UF  [C0402]  67.03 209.55 90 top
C48  0.1UF  [C0402]  68.3 209.55 90 top
C49  0.1UF  [C0402]  69.32 209.55 90 top
C50  10UF  [C1206]  17.73 211.46 180 top
C51  0.1UF  [C0402]  167.65 217.81 270 top
C52  1UF  [C0603]  29.47 203.2 90 top
C53  0.1UF  [C0603]  31 203.2 90 top
C54  1000PF  [C0402]  162.44 215.14 270 top
C55  0.1UF  [C0402]  163.46 215.14 270 top
C56  0.1UF  [C0402]  52.23 209.55 90 top
C57  0.1UF  [C0402]  53.24 209.55 90 top
C58  0.1UF  [C0402]  54.33 209.55 90 top
C59  22NF  [C0402]  127.77 202.56 0 top
C60  47UF  [C1206]  128.41 204.34 0 top
C61  0.1UF  [C0402]  51.95 195.33 90 top
C62  2.2PF  [C0603]  27.95 203.2 90 top
C63  1UF  [C0402]  45.73 195.07 90 top
C64  0.1UF  [C0402]  47 195.07 90 top
C66  2.2PF  [C0603]  68.15 196.02 90 top
C67  2.2PF  [C0603]  49.86 197.55 0 top
C68  0.1UF  [C0402]  50.81 195.33 90 top
C69  0.1UF  [C0603]  69.67 196.02 90 top
C70  1UF  [C0603]  71.19 196.02 90 top
C71  1.0PF  [C0603]  44.4 195.2 90 top
C72  0.22UF  [C0402]  121.55 190.12 135 top
C73  0.1UF  [C0402]  120.79 189.36 135 top
C74  0.022UF  [C0603]  111.9 187.71 180 top
C75  0.22UF  [C0402]  120.03 188.59 135 top
C76  0.22UF  [C0603]  9.92 188.47 270 top
C77  0.22UF  [C0402]  119.26 187.83 135 top
C78  0.22UF  [C0402]  118.5 187.07 135 top
C79  10UF  [C0805]  111.52 185.8 180 top
C80  0.22UF  [C0402]  117.74 186.31 135 top
C81  0.01UF  [C0402]  116.98 185.55 135 top
C82  0.1UF  [C0402]  6.36 189.74 180 top
C83  4.7UF  [C0805]  9.92 185.04 270 top
C84  22UF  [C0805]  62.43 176.47 90 top
C85  3900PF  [C0402]  110.5 179.4 270 top
C86  3900PF  [C0402]  111.52 179.4 270 top
C87  0.1UF  [C0402]  53.6 176.78 270 top
C88  2.2PF  [C0603]  27.82 175.26 270 top
C89  0.1UF  [C0402]  43.06 174.75 270 top
C90  4.7UF  [C0603]  76.46 169.8 180 top
C91  1UF  [C0402]  186.95 167.13 0 top
C92  1UF  [C0402]  186.95 165.61 0 top
C93  1UF  [C0402]  188.73 162.56 90 top
C94  0.1UF  [C0402]  29.09 175.39 270 top
C95  0.1UF  [C0402]  30.11 175.39 270 top
C96  180PF  [C0402]  155.33 162.13 90 top
C97  180PF  [C0402]  160.26 162.08 90 top
C98  4.7UF  [C0603]  73.04 170.05 0 top
C99  2.2UF  [C0603]  63.38 168.15 90 top
C100  2.2UF  [C0603]  57.41 167.51 90 top
C101  4.7UF  [C0603]  66.18 168.91 0 top
C102  1UF  [C0402]  165.54 163.22 135 top
C103  2.2UF  [C0603]  61.3 167.74 0 top
C104  0.1UF  [C0402]  65.92 167.39 0 top
C105  0.1UF  [C0402]  73.92 165.61 0 top
C106  0.1UF  [C0402]  73.92 164.34 0 top
C107  0.1UF  [C0402]  73.92 163.07 0 top
C108  0.1UF  [C0402]  186.95 145.29 90 top
C109  0.1UF  [C0402]  20.08 145.54 180 top
C110  1UF  [C0402]  22.87 148.34 90 top
C111  10UF  [C0603]  26.81 142.49 270 top
C112  10UF  [C0603]  28.33 142.49 270 top
C113  10UF  [C0603]  20.2 142.37 270 top
C114  0.1UF  [C0402]  186.95 136.91 90 top
C115  0.1UF  [C0402]  37.86 131.19 90 top
C116  0.1UF  [C0402]  191.27 144.4 270 top
C117  1000PF  [C0402]  186.95 143.13 270 top
C118  0.1UF  [C0402]  16.27 131.95 0 top
C119  0.1UF  [C0402]  37.6 136.78 90 top
C120  1UF  [C0402]  158.79 135.41 315 top
C121  4.7UF  [C0603]  59.42 129.34 180 top
C122  1UF  [C0603]  12.58 130.3 0 top
C123  0.1UF  [C0402]  163 136.19 270 top
C124  0.1UF  [C0402]  191.15 136.14 270 top
C125  1000PF  [C0402]  186.95 134.62 270 top
C126  4.7UF  [C0603]  21.71 125.08 270 top
C127  0.1UF  [C0402]  81.54 132.97 270 top
C128  2.2UF  [C0603]  16.65 127.64 90 top
C129  0.1UF  [C0402]  44.66 132.08 270 top
C130  0.1UF  [C0402]  45.68 132.08 270 top
C131  0.1UF  [C0402]  46.9 132.08 270 top
C132  0.1UF  [C0402]  47.92 132.08 270 top
C133  0.1UF  [C0402]  48.93 132.08 270 top
C134  0.1UF  [C0402]  49.95 132.08 270 top
C135  0.1UF  [C0402]  50.96 132.08 270 top
C136  0.1UF  [C0402]  51.98 132.08 270 top
C137  0.1UF  [C0402]  53 132.08 270 top
C138  0.1UF  [C0402]  54.01 132.08 270 top
C139  0.1UF  [C0402]  18.43 124.84 90 top
C140  4.7UF  [C0603]  20.71 122.68 0 top
C141  1UF  [C0402]  107.66 104.11 90 top
C142  1UF  [C0402]  112.99 103.86 90 top
C143  4.7UF  [C0603]  118.12 105.54 180 top
C144  10UF  [C0603]  113.24 106.53 270 top
C145  10UF  [C0603]  114.9 106.53 270 top
C146  4.7UF  [C0603]  113.29 109.86 90 top
C147  4.7UF  [C0603]  114.82 109.86 90 top
C148  0.1UF  [C0402]  92.21 102.62 0 top
C149  4.7UF  [C0603]  121.42 108.84 0 top
C150  0.1UF  [C0402]  107.58 111.63 270 top
C151  22UF  [C0805]  36.08 108.01 0 top
C152  10UF  [C0805]  121.42 101.85 0 top
C153  0.1UF  [C0402]  73.16 100.58 0 top
C154  4.7UF  [C0603]  118.12 103.89 180 top
C155  22UF  [C0805]  33.98 102.04 270 top
C156  4.7UF  [C0603]  121.42 107.19 0 top
C157  0.1UF  [C0402]  26.62 102.43 270 top
C158  0.1UF  [C0402]  30.05 102.43 270 top
C159  0.1UF  [C0402]  32.21 102.43 270 top
C160  4.7UF  [C0603]  121.42 103.89 0 top
C161  4.7UF  [C0603]  121.42 105.54 0 top
C162  10UF  [C0603]  111.39 101.98 0 top
C163  0.1UF  [C0402]  31.76 98.17 180 top
C164  0.1UF  [C0402]  106.44 97.28 0 top
C165  2.2UF  [C0603]  38.36 96.84 180 top
C166  22UF  [C1206]  121.93 99.44 0 top
C167  0.1UF  [C0402]  41.03 93.98 0 top
C168  2.2UF  [C0603]  33.54 94.61 270 top
C169  0.1UF  [C0402]  35.76 102.43 270 top
C170  0.1UF  [C0402]  28.65 96.96 90 top
C171  0.1UF  [C0402]  29.79 96.96 90 top
C172  0.1UF  [C0402]  37.22 94.36 270 top
C173  0.1UF  [C0402]  38.24 94.36 270 top
C174  0.1UF  [C0402]  39.25 94.36 270 top
C175  0.1UF  [C0402]  42.62 97.98 0 top
C176  0.1UF  [C0402]  35.44 97.16 0 top
C177  0.1UF  [C0402]  23.89 90.42 180 top
C178  0.1UF  [C0402]  35.44 96.01 0 top
C179  0.1UF  [C0402]  26.55 89.53 180 top
C180  0.1UF  [C0402]  23.89 89.41 180 top
C181  2.2PF  [C0603]  47.57 89.53 180 top
C182  0.1UF  [C0402]  35.44 95 0 top
C183  0.1UF  [C0402]  41.03 95 0 top
C184  0.1UF  [C0603]  145.93 50.93 270 top
C185  0.1UF  [C0402]  74.56 91.44 90 top
C186  0.1UF  [C0402]  97.04 84.07 180 top
C187  22PF  [C0402]  94.85 84.04 180 top
C188  1000PF  [C0603]  147.58 50.93 270 top
C189  0.1UF  [C0402]  101.1 84.58 270 top
C190  0.1UF  [C0402]  102.12 84.58 270 top
C191  0.1UF  [C0402]  103.13 84.58 270 top
C192  0.1UF  [C0402]  104.15 84.58 270 top
C193  0.1UF  [C0402]  105.17 84.58 270 top
C194  0.1UF  [C0402]  106.18 84.58 270 top
C195  0.1UF  [C0402]  107.2 84.58 270 top
C196  0.1UF  [C0402]  108.21 84.58 270 top
C197  0.1UF  [C0402]  140.85 84.33 270 top
C198  15PF  [C0402]  112.91 86.11 90 top
C199  22UF  [C1206]  87.01 87.38 90 top
C200  1UF  [C0402]  144.28 84.33 90 top
C201  1UF  [C0402]  76.59 76.33 90 top
C202  1UF  [C0402]  77.73 76.33 90 top
C203  2.2UF  [C0603]  75.19 76.2 90 top
C204  15PF  [C0402]  111.26 84.71 0 top
C205  22PF  [C0402]  90.54 84.04 0 top
C206  1UF  [C0402]  88.17 83.91 0 top
C207  0.1UF  [C0402]  88.17 82.7 0 top
C208  22UF  [C0805]  98.56 82.3 0 top
C209  10UF  [C0603]  69.23 71.12 0 top
C210  22PF  [C0402]  119.52 67.18 180 top
C211  0.1UF  [C0402]  78.62 63.25 90 top
C212  0.1UF  [C0402]  79.64 63.25 90 top
C213  10UF  [C0603]  76.97 63.5 90 top
C214  0.01UF  [C0402]  139.77 65.6 180 top
C215  0.01UF  [C0402]  139.77 64.58 180 top
C216  1UF  [C0402]  112.15 68.96 90 top
C217  0.1UF  [C0402]  113.29 68.96 90 top
C218  0.1UF  [C0402]  114.44 68.96 90 top
C219  1UF  [C0402]  115.58 68.96 90 top
C220  22UF  [C0805]  117.36 69.72 90 top
C221  10UF  [C0603]  66.18 64.52 180 top
C222  22PF  [C0402]  114.95 67.18 0 top
C223  10UF  [C0603]  78.12 69.98 270 top
C224  10UF  [C0603]  79.64 69.98 270 top
C225  10UF  [C0603]  66.18 62.87 180 top
C226  1UF  [C0402]  65.92 69.09 270 top
C227  0.1UF  [C0402]  70.75 69.09 270 top
C228  0.01UF  [C0402]  131.84 65.66 180 top
C229  0.01UF  [C0402]  136.03 65.66 180 top
C230  0.01UF  [C0402]  131.84 64.64 180 top
C231  0.01UF  [C0402]  136.03 64.64 180 top
C232  0.1UF  [C0402]  161.17 67.31 180 top
C233  0.1UF  [C0402]  159.9 58.67 270 top
C234  1000PF  [C0402]  160.92 58.67 270 top
C235  0.01UF  [C0402]  129.68 56.45 180 top
C236  1000PF  [C0402]  161.17 66.17 180 top
C237  0.01UF  [C0402]  129.68 55.37 180 top
C238  10UF  [C1206]  163.59 65.53 270 top
C239  22UF  [C0805]  170.83 53.85 0 top
C240  10UF  [C0805]  35.06 58.99 0 top
C241  0.1UF  [C0402]  54.75 62.36 270 top
C242  0.1UF  [C0402]  65.29 53.85 270 top
C243  0.1UF  [C0402]  77.61 58.55 180 top
C244  2.2UF  [C0603]  77.86 60.83 270 top
C245  0.1UF  [C0402]  29.47 55.75 90 top
C246  0.1UF  [C0402]  30.49 55.75 90 top
C247  22PF  [C0402]  27.57 50.8 0 top
C248  0.1UF  [C0402]  79.64 60.96 270 top
C249  10UF  [C0805]  21.98 56.32 90 top
C250  0.1UF  [C0402]  77.61 57.53 180 top
C251  10UF  [C0805]  35.06 56.77 0 top
C252  2.2UF  [C0603]  16.9 51.18 270 top
C253  0.1UF  [C0402]  77.61 56.52 180 top
C254  0.1UF  [C0603]  144.79 46.35 90 top
C255  22PF  [C0402]  95.51 45.21 90 top
C256  10UF  [C1206]  163.59 59.94 270 top
C257  0.1UF  [C0402]  77.61 53.98 180 top
C258  22UF  [C1210]  122.57 47.24 270 top
C259  22PF  [C0402]  80.4 45.87 180 top
C260  0.1UF  [C0402]  77.61 52.7 180 top
C261  150PF  [C0402]  90.43 42.29 90 top
C262  22UF  [C0805]  158.76 51.44 180 top
C263  0.1UF  [C0603]  184.29 51.56 180 top
C264  0.1UF  [C0402]  123.33 43.69 180 top
C265  1UF  [C0805]  183.78 49.78 180 top
C266  1UF  [C0603]  187.72 38.48 90 top
C267  22PF  [C0402]  55.7 42.74 270 top
C268  1UF  [C0402]  76.59 49.78 270 top
C269  0.1UF  [C0402]  77.86 49.78 270 top
C270  2.2UF  [C0603]  21.35 49.02 270 top
C271  0.01UF  [C0402]  145.81 41.4 270 top
C272  0.1UF  [C0402]  55.26 38.99 180 top
C273  22PF  [C0402]  78.12 45.87 0 top
C274  1UF  [C0603]  29.92 44.07 0 top
C275  10UF  [C0805]  21.85 43.31 180 top
C276  470PF  [C0402]  109.61 41.02 90 top
C277  0.1UF  [C0402]  167.9 43.43 180 top
C278  0.1UF  [C0402]  123.01 35.37 0 top
C279  22PF  [C0402]  96.53 45.21 270 top
C280  150PF  [C0402]  99.77 45.21 270 top
C281  10UF  [C0805]  18.43 35.81 270 top
C282  470NF  [C0603]  20.2 35.94 270 top
C283  10UF  [C0805]  17.41 43.75 270 top
C284  0.1UF  [C0402]  23.63 35.05 270 top
C285  2200PF  [C0402]  57.92 39.24 0 top
C286  0.1UF  [C0402]  30.41 42.11 270 top
C287  0.1UF  [C0402]  125.04 32.26 180 top
C288  2200PF  [C0402]  57.92 38.23 0 top
C289  0.1UF  [C0402]  120.53 27.94 90 top
C290  0.1UF  [C0402]  158.51 41.15 270 top
C291  2200PF  [C0402]  57.92 37.21 0 top
C292  0.1UF  [C0402]  125.04 30.29 180 top
C293  2200PF  [C0402]  57.92 36.2 0 top
C294  4.7UF  [C0603]  129.93 33.27 0 top
C295  0.1UF  [C0402]  55.26 34.92 0 top
C296  0.1UF  [C0402]  125.34 35.31 180 top
C297  0.1UF  [C0402]  72.02 26.16 180 top
C298  0.1UF  [C0402]  144.92 26.16 180 top
C299  0.1UF  [C0402]  129.61 31.94 0 top
C300  0.1UF  [C0402]  36.71 24.46 180 top
C301  100UF  [DEC063D70H]  18.3 23.09 270 top
C302  0.1UF  [C0402]  24.39 24 180 top
C303  0.1UF  [C0603]  162.19 17.02 0 top
C304  0.1UF  [C0402]  129.11 28.96 0 top
C305  0.1UF  [C0402]  146.57 26.54 90 top
C306  0.1UF  [C0402]  125.04 28.32 180 top
C307  0.1UF  [C0402]  117.74 27.5 180 top
C308  0.1UF  [C0402]  117.74 26.29 180 top
C309  0.1UF  [C0603]  157.55 24.45 0 top
C310  0.1UF  [C0402]  27.19 24 0 top
C311  0.1UF  [C0402]  66.18 18.03 270 top
C312  22UF  [C0805]  63.89 21.72 180 top
C313  470PF  [C0402]  112.66 19.3 90 top
C314  0.1UF  [C0402]  122.57 23.75 270 top
C315  0.1UF  [C0402]  123.58 23.75 270 top
C316  0.1UF  [C0402]  124.6 23.75 270 top
C317  0.01UF  [C0603]  156.6 18.67 180 bottom
C318  0.1UF  [C0402]  123.33 20.7 270 top
C319  220UF  [DEC063D110H]  23.51 9.65 270 top
C320  0.1UF  [C0402]  72.91 12.57 270 top
C321  470PF  [C0402]  114.31 7.11 90 top
C322  4.7UF  [C0805]  150.7 12.19 0 top
C323  0.1UF  [C0402]  51.19 7.62 0 top
C324  4.7UF  [C0805]  150.7 10.16 0 top
C325  0.1UF  [C0402]  40.78 9.27 90 top
C326  220UF  [DEC063D110H]  20.71 3.76 270 top
C327  0.1UF  [C0402]  75.96 9.14 90 top
C328  100UF  [TC352819B]  74.43 4.83 270 top
C329  100UF  [TC352819B]  86.24 4.83 270 top
C330  0.1UF  [C0402]  51.19 11.3 180 top
C331  0.1UF  [C0603]  154.44 12.19 270 top
C332  100UF  [TC352819B]  61.42 4.19 270 top
C333  100UF  [TC352819B]  49.79 4.06 270 top
C334  220PF  [C0402]  151.65 8 90 top
C335  220PF  [C0402]  152.73 8 90 top
C336  220PF  [C0402]  154.19 8 90 top
C337  220PF  [C0402]  155.46 8 90 top
C338  220PF  [C0402]  156.73 8 90 top
C339  220PF  [C0402]  158 8 90 top
C340  220PF  [C0402]  159.27 8 90 top
C341  220PF  [C0402]  160.54 8 90 top
C342  0.1UF  [C0603]  162.19 15.43 0 top
C343  0.1UF  [C0402]  63.89 6.86 90 top
C344  0.1UF  [C0402]  88.78 6.86 90 top
C345  10UF  [C1206]  156.35 11.94 270 top
C346  1UF  [C0603]  170.19 5.71 270 top
C347  0.1UF  [C0402]  78.37 226.19 270 bottom
C348  3.3PF  [C0402]  21.22 212.85 180 bottom
C349  1UF  [C0402]  50.56 191.9 0 bottom
C350  1UF  [C0402]  26.68 180.72 90 bottom
C351  1000PF  [C0402]  114.77 181.15 180 bottom
C352  0.1UF  [C0402]  114.77 180.14 180 bottom
C353  0.1UF  [C0402]  26.81 183.64 90 bottom
C354  1.0PF  [C0603]  25.47 183.71 90 bottom
C355  1UF  [C0402]  24.2 183.64 90 bottom
C356  2.2UF  [C0603]  66.05 170.18 90 bottom
C357  3300PF  [C0402]  112.15 176.78 180 bottom
C358  0.22UF  [C0402]  112.15 175.64 180 bottom
C359  180PF  [C0402]  111.86 166.02 180 bottom
C360  2.2UF  [C0603]  102.18 170.69 90 bottom
C361  220NF  [C0603]  130.95 162.2 90 bottom
C362  2.2UF  [C0603]  62.49 170.18 90 bottom
C363  0.22UF  [C0402]  111.14 164.27 180 bottom
C364  4.7UF  [C0805]  125.54 160.81 90 bottom
C365  0.01UF  [C0603]  120.91 161.04 90 bottom
C366  0.01UF  [C0603]  118.12 161.04 90 bottom
C367  0.1UF  [C0402]  80.27 162.81 0 bottom
C368  0.1UF  [C0402]  63.76 167.13 90 bottom
C369  470PF  [C0402]  8.01 161.29 180 bottom
C370  22UF  [C0805]  98.82 166.24 90 bottom
C371  470PF  [C0402]  8.01 160.02 180 bottom
C372  2.2UF  [C0603]  61.48 165.1 90 bottom
C373  1UF  [C0402]  129.93 158.24 180 bottom
C374  4.7UF  [C0603]  190.38 167.89 270 bottom
C375  1UF  [C0402]  129.93 157.23 180 bottom
C376  2.2UF  [C0603]  129.8 159.51 0 bottom
C377  180PF  [C0402]  129.93 155.96 180 bottom
C378  2.2UF  [C0603]  55.26 160.78 90 bottom
C379  0.1UF  [C0402]  59.19 159.89 0 bottom
C380  0.22UF  [C0402]  111.58 162.75 270 bottom
C381  1UF  [C0402]  58.18 154.81 270 bottom
C382  22UF  [C0805]  115.26 162.31 270 bottom
C383  10UF  [C0805]  113.17 162.31 270 bottom
C384  4.7UF  [C0603]  52.72 156.97 225 bottom
C385  180PF  [C0402]  128.56 162.23 270 bottom
C386  0.1UF  [C0402]  59.19 158.88 0 bottom
C387  4.7UF  [C0805]  125.94 157.78 0 bottom
C388  22UF  [C1206]  129.3 153.92 180 bottom
C389  0.1UF  [C0402]  55.64 153.54 225 bottom
C390  1UF  [C0402]  53.6 155.32 180 bottom
C391  0.1UF  [C0402]  62.87 153.12 90 bottom
C392  22UF  [C1206]  129.3 151.38 180 bottom
C393  0.1UF  [C0402]  53.6 154.05 180 bottom
C394  10UF  [C0603]  63.81 146.52 0 bottom
C395  0.1UF  [C0402]  57.92 152.91 180 bottom
C396  10UF  [C0805]  129.8 146.3 180 bottom
C397  0.1UF  [C0402]  67.35 152.6 0 bottom
C398  22UF  [C1206]  129.3 148.84 180 bottom
C399  0.1UF  [C0402]  62.38 151.42 180 bottom
C400  0.1UF  [C0402]  59.55 149.52 90 bottom
C401  10UF  [C0603]  58.94 151.43 180 bottom
C402  1UF  [C0402]  60.08 144.53 0 bottom
C403  0.1UF  [C0402]  62.43 150.42 180 bottom
C404  0.1UF  [C0402]  60.21 143.51 0 bottom
C405  220NF  [C0603]  125.03 152.68 270 bottom
C406  0.1UF  [C0402]  59.6 147.46 90 bottom
C407  4.7UF  [C0603]  190.13 139.7 90 bottom
C408  0.1UF  [C0402]  60.21 142.49 0 bottom
C409  0.1UF  [C0402]  61.1 146.05 90 bottom
C410  0.1UF  [C0402]  66.18 149.99 270 bottom
C411  22UF  [C1206]  129.42 143.64 180 bottom
C412  0.1UF  [C0402]  59.51 145.92 180 bottom
C413  0.1UF  [C0402]  70.11 138.56 180 bottom
C414  0.1UF  [C0402]  65.03 144.91 180 bottom
C415  2.2UF  [C0603]  129.93 141.16 0 bottom
C416  4.7UF  [C0805]  112.74 143.87 270 bottom
C417  0.1UF  [C0402]  72.65 138.63 0 bottom
C418  470NF  [C0402]  132.22 141.22 270 bottom
C419  0.1UF  [C0402]  58.89 137.11 180 bottom
C420  10UF  [C0603]  83.83 127.64 90 bottom
C421  4.7UF  [C0603]  59.04 135.79 180 bottom
C422  10UF  [C0603]  88.4 129.67 180 bottom
C423  10UF  [C0603]  91.7 128.52 0 bottom
C424  0.01UF  [C0402]  111.9 124.33 180 bottom
C425  180PF  [C0402]  96.91 123.88 180 bottom
C426  180PF  [C0402]  103.64 123.83 180 bottom
C427  0.01UF  [C0402]  111.9 123.19 180 bottom
C428  4.7UF  [C0603]  84.15 131.19 270 bottom
C429  180PF  [C0402]  100.34 122.81 180 bottom
C430  1UF  [C0402]  85.86 129.67 0 bottom
C431  0.22UF  [C0402]  91.96 132.59 270 bottom
C432  0.22UF  [C0402]  90.94 132.59 270 bottom
C433  390PF  [C0402]  87.01 131.44 270 bottom
C434  10UF  [C0603]  93.23 132.4 270 bottom
C435  22UF  [C0805]  99.32 130.68 270 bottom
C436  22UF  [C0805]  97.17 130.68 270 bottom
C437  22UF  [C0805]  95.01 130.68 270 bottom
C438  0.1UF  [C0402]  101.1 130.81 270 bottom
C439  1UF  [C0402]  86.24 124.21 0 bottom
C440  0.1UF  [C0402]  34.94 108.52 90 bottom
C441  0.1UF  [C0402]  104.79 109.73 90 bottom
C442  27PF  [C0603]  41.22 99.89 270 bottom
C443  27PF  [C0603]  41.22 102.81 90 bottom
C444  0.1UF  [C0402]  14.23 98.55 270 bottom
C445  0.01UF  [C0402]  76.85 91.69 180 bottom
C446  100UF  [TC352819B]  9.6 92.65 180 bottom
C447  0.1UF  [C0402]  35.98 83.57 180 bottom
C448  0.1UF  [C0402]  88.17 83.91 0 bottom
C449  2.2PF  [C0603]  51.64 88.07 90 bottom
C450  0.1UF  [C0402]  49.97 87.5 90 bottom
C451  1UF  [C0402]  88.17 82.7 0 bottom
C452  100UF  [TC352819B]  17.16 79.25 0 bottom
C453  0.1UF  [C0402]  38.49 85.34 90 bottom
C454  10UF  [C0603]  90.69 82.68 180 bottom
C455  2.2UF  [C0603]  95.2 82.36 180 bottom
C456  0.1UF  [C0402]  95.45 81.09 180 bottom
C457  0.1UF  [C0402]  84.47 71.25 90 bottom
C458  2.2UF  [C0603]  83.07 71.75 90 bottom
C459  0.1UF  [C0402]  94.88 78.93 90 bottom
C460  2.2UF  [C0603]  90.69 81.03 180 bottom
C461  2.2UF  [C0603]  102.56 79.44 90 bottom
C462  0.1UF  [C0402]  41.91 83.93 270 bottom
C463  0.1UF  [C0402]  40.77 83.93 270 bottom
C464  0.1UF  [C0402]  90.82 79.76 180 bottom
C465  4.7UF  [C0603]  107.64 77.03 90 bottom
C466  1UF  [C0402]  87.26 76.2 90 bottom
C467  1UF  [C0402]  86.24 76.2 90 bottom
C468  2.2UF  [C0603]  87.64 72.52 270 bottom
C469  0.1UF  [C0402]  101.99 77.03 180 bottom
C470  2.2UF  [C0603]  94.94 77.15 180 bottom
C471  0.1UF  [C0402]  105.8 73.91 90 bottom
C472  0.1UF  [C0402]  104.79 73.91 90 bottom
C473  0.1UF  [C0402]  14.23 76.83 270 bottom
C474  0.1UF  [C0402]  96.78 73.28 180 bottom
C475  0.1UF  [C0402]  99.83 70.74 90 bottom
C476  1UF  [C0402]  96.79 71.59 180 bottom
C477  0.1UF  [C0402]  96.47 69.66 90 bottom
C478  0.1UF  [C0402]  18.68 73.98 270 bottom
C479  1UF  [C0402]  97.55 68.58 90 bottom
C480  10UF  [C0603]  97.84 64.96 270 bottom
C481  0.1UF  [C0402]  103.26 63.63 270 bottom
C482  2.2UF  [C0603]  108.98 62.74 270 bottom
C483  1UF  [C0402]  79.13 71.12 270 bottom
C484  1UF  [C0402]  78.12 71.12 270 bottom
C485  22UF  [C0805]  24.39 61.59 180 bottom
C486  1UF  [C0402]  96.02 65.91 180 bottom
C487  0.1UF  [C0402]  94.25 58.04 180 bottom
C488  0.1UF  [C0402]  95.39 64.9 180 bottom
C489  0.1UF  [C0402]  77.61 57.53 180 bottom
C490  100PF  [C0402]  16.39 66.42 270 bottom
C491  100PF  [C0402]  13.85 62.99 0 bottom
C492  1UF  [C0402]  97.67 52.58 180 bottom
C493  1UF  [C0402]  23.25 57.53 90 bottom
C494  2.2UF  [C0603]  77.61 56.26 180 bottom
C495  0.1UF  [C0402]  99.58 58.93 0 bottom
C496  0.1UF  [C0402]  89.04 50.29 180 bottom
C497  22UF  [C1206]  102.25 52.7 180 bottom
C498  2.2UF  [C0603]  93.36 52.2 180 bottom
C499  100PF  [C0402]  12.84 52.2 90 bottom
C500  2.2UF  [C0603]  72.27 50.29 0 bottom
C501  22UF  [C1210]  123.96 47.24 270 bottom
C502  4.7UF  [C0805]  20.33 42.93 90 bottom
C503  0.1UF  [C0402]  100.72 55.75 270 bottom
C504  100PF  [C0402]  12.84 46.48 270 bottom
C505  0.1UF  [C0402]  126.88 40.77 90 bottom
C506  4.7UF  [C0805]  17.41 48.01 90 bottom
C507  10UF  [C0805]  17.16 39.5 90 bottom
C508  0.1UF  [C0402]  81.42 52.32 270 bottom
C509  0.1UF  [C0402]  79 52.32 270 bottom
C510  0.01UF  [C0402]  186.7 46.74 90 bottom
C511  0.1UF  [C0402]  48.4 41.15 180 bottom
C512  0.1UF  [C0402]  125.87 36.96 90 bottom
C513  4.7UF  [C0603]  127.14 37.34 90 bottom
C514  100UF  [TC352819B]  181.87 63.12 270 bottom
C515  0.1UF  [C0402]  20.84 45.47 180 bottom
C516  2.2UF  [C0603]  88.96 48.13 270 bottom
C517  0.1UF  [C0402]  42.05 39.24 270 bottom
C518  0.22UF  [C0402]  23.12 38.54 270 bottom
C519  470NF  [C0603]  21.85 38.73 270 bottom
C520  1UF  [C0603]  18.93 39.24 90 bottom
C521  1UF  [C0402]  116.35 31.83 180 bottom
C522  0.1UF  [C0402]  116.35 30.81 180 bottom
C523  0.1UF  [C0603]  176.92 63.94 0 top
C524  1000PF  [C0603]  176.92 62.23 0 top
C525  33PF  [C0402]  128.66 30.73 270 bottom
C526  0.1UF  [C0402]  52.21 35.05 0 bottom
C527  0.1UF  [C0402]  116.98 34.29 0 bottom
C528  10UF  [C0805]  52.08 33.53 0 bottom
C529  0.1UF  [C0402]  116.98 33.27 0 bottom
C530  33PF  [C0402]  128.66 28.19 90 bottom
C531  10UF  [C0603]  91.51 127 0 bottom
C532  0.01UF  [C0402]  23.76 25.91 180 bottom
C533  10UF  [C0603]  48.4 29.46 180 bottom
C534  0.22UF  [C0402]  23.38 28.45 180 bottom
C535  470NF  [C0603]  23.32 27.18 180 bottom
C536  2.2PF  [C0603]  25.79 22.42 270 bottom
C537  100PF  [C0402]  106.94 17.04 90 bottom
C538  22UF  [C1206]  102.12 17.02 0 bottom
C539  0.1UF  [C0402]  38.87 18.8 270 bottom
C540  0.1UF  [C0402]  35.93 18.49 270 bottom
C541  0.1UF  [C0402]  34.85 18.49 270 bottom
C542  0.1UF  [C0402]  46.62 20.83 90 bottom
C543  0.1UF  [C0402]  45.6 20.83 90 bottom
C544  2.2PF  [C0603]  44.33 20.83 90 bottom
C545  0.1UF  [C0402]  145.3 15.88 0 bottom
C546  22UF  [C1206]  101.74 12.95 0 bottom
C547  0.01UF  [C0402]  23.76 24.89 0 bottom
C548  0.1UF  [C0402]  147.58 15.88 180 bottom
C549  0.1UF  [C0402]  143.14 15.88 180 bottom
C550  0.1UF  [C0402]  31.51 12.64 90 bottom
C551  0.1UF  [C0603]  153.62 20.7 270 bottom
C552  470PF  [C0402]  15.38 6.86 0 bottom
C553  100PF  [C0402]  106.5 12.32 180 bottom
C554  0.1UF  [C0402]  61.92 165.35 90 top
C555  10UF  [C0603]  91.77 130.05 0 bottom
C556  0.01UF  [C0402]  80.66 203.07 0 top
C557  1UF  [C0402]  80.66 201.8 0 top
C1457  100PF  [C0402]  45.86 37.66 0 bottom
C1458  100PF  [C0402]  45.86 36.45 0 bottom
C1459  100PF  [C0402]  48.65 35.43 0 bottom
C1460  100PF  [C0402]  40.9 33.27 180 bottom
C1462  2.2UF  [C0603]  94.94 28.38 0 bottom
C1463  27PF  [C0402]  101.61 45.21 270 bottom
C1464  4.7UF  [C0805]  111.96 174.12 180 bottom
C1465  1UF  [C0402]  98.44 114.68 180 bottom
CN1  MXM314+5P  [SLT_MXM-3_314_ACES_1]  60 218.32 180 top
CN2  PCI-E52P+4P  [SCON_MINIPCI_52_ACES]  38.08 83.36 0 top
CN5  PCI-E52P+4P  [SCON_MINIPCI_52_ACES]  36.53 18.14 0 top
CN6  WFR30P  [SWAF30_100P580W1730L]  75.58 189.99 0 top
CN7  WFR2X20P  [SCON_B2B_40_AUK]  54.49 189.99 0 top
CN8  WFR30P  [SWAF30_100P580W1730L]  23.25 196.09 270 top
CN9  WFR2X20P  [SCON_B2B_40_AUK]  23.25 173.23 270 top
CN10  WFR4P+2P  [SWAF4_100P290W600L]  31.25 9.27 0 top
CN11  SATA7P+2P  [DCON_SATABOX_7_HOMETOM]  135.9 59.69 0 top
CN12  SATA7P+2P  [DCON_SATABOX_7_HOMETOM]  136.15 70.48 180 top
CN13  SKT42P+2P  [SCON_SKT_MEMARY-CARD_40_TAI]  26.25 130.62 90 bottom
CN14  USB-A4P+2P  [DCON_USBX1_4_FOXCONN]  9.25 102.62 90 bottom
CN15  USB-A4P+2P  [DCON_USBX1_4_FOXCONN]  9.25 82.57 90 bottom
CN16  USB-A4P+2P  [DCON_USBX1_4_AUK_3]  57.11 8.42 90 top
CN17  USB-A4P+2P  [DCON_USBX1_4_AUK_3]  69.61 8.42 90 top
CN18  USB-A4P+2P  [DCON_USBX1_4_AUK_3]  82.11 8.42 90 top
CN19  USB-A4P+2P  [DCON_USBX1_4_AUK_3]  94.61 8.42 90 top
CN20  AUDIO  [DCON_PLUG-AUD_8_SINGATRON]  2.8 65.4 270 bottom
CN21  AUDIO  [DCON_PLUG-AUD_8_SINGATRON]  2.8 50.4 270 bottom
CN22  AUDIO  [DCON_JACK_PLUG_5_HOMETOM]  106.9 4.92 0 top
CN23  RJ45  [DCON_RJ45LEDX2_14_UDE_3]  124.5 8.95 180 top
CN24  DC  [DCON_POWER-JACK_2_SINGATRON]  143.1 5.42 0 top
CN25  WFR8P  [SWAF8_100P290W1000L_AUK]  42.56 3.17 0 top
CN26  WFR6P+2P  [SWAF6_100P290W800L]  75.19 86.61 0 top
CN27  WFR14P+2P  [SWAF14_125P370W2225L]  190.13 57.28 90 top
